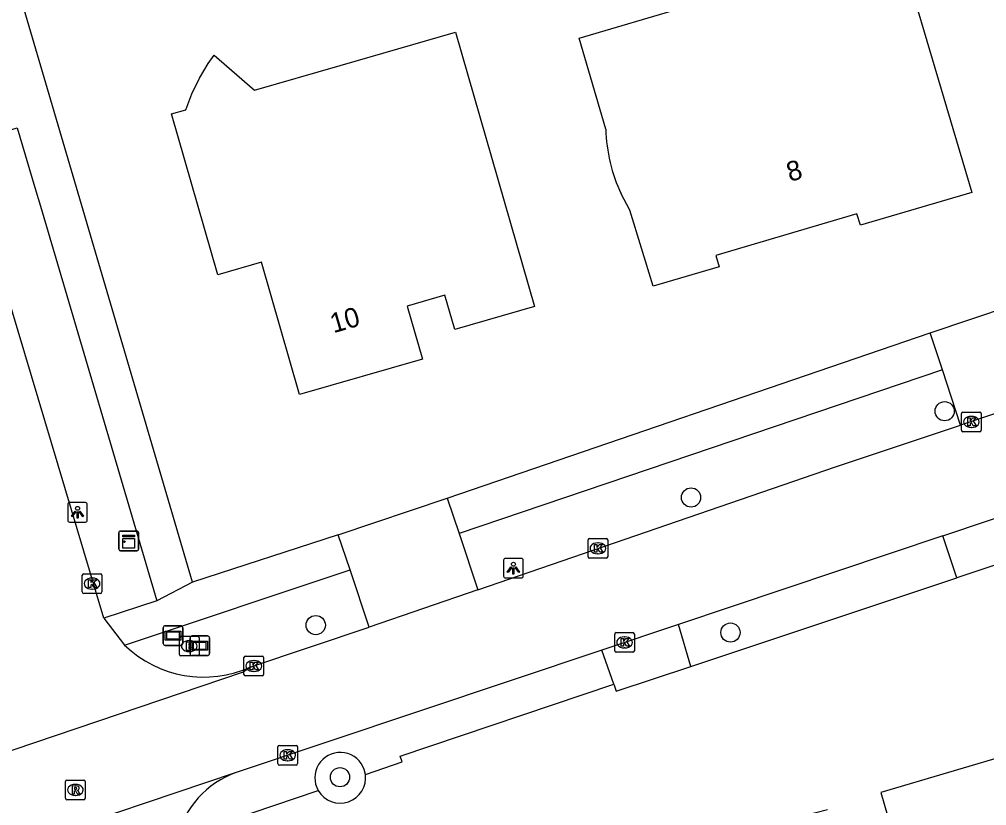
# Model space of a CAD drawing. Extents: x 162417 to 163721, y 384268 to 385416.
# Drawn here: x 163324.7 to 163373.92, y 384590.69 to 384630.72 of the extents above; entities that cross this region are included whole.
import ezdxf

# ---------------------------------------------------------------- set-up
doc = ezdxf.new("R2010")
doc.units = 0
for name, color, linetype in [('IMGEO_Boom', 7, 'Continuous'), ('IMGEO_Brandkraan', 7, 'Continuous'), ('IMGEO_Fietspad_open', 7, 'Continuous'), ('IMGEO_Groenvoorziening', 7, 'Continuous'), ('IMGEO_Haag', 7, 'Continuous'), ('IMGEO_Kast', 7, 'Continuous'), ('IMGEO_Kolk', 7, 'Continuous'), ('IMGEO_Lichtpunt', 7, 'Continuous'), ('IMGEO_Pand', 7, 'Continuous'), ('IMGEO_Pand_nummerreeks', 7, 'Continuous'), ('IMGEO_Rijbaan_lokaal_open', 7, 'Continuous'), ('IMGEO_Rioolput', 7, 'Continuous'), ('IMGEO_Straatnaambord', 7, 'Continuous'), ('IMGEO_Verklikker', 7, 'Continuous'), ('IMGEO_Voetpad_open', 7, 'Continuous')]:
    doc.layers.add(name, color=color, linetype=linetype)

msp = doc.modelspace()

# ---------------------------------------------------------------- linework, layer by layer
at = {"layer": 'IMGEO_Boom'}
for centre in [(163371.785, 384610.77), (163358.881, 384606.376), (163339.782, 384599.881), (163360.886, 384599.501), (163341.015, 384592.136)]:
    msp.add_circle(centre, 0.489, dxfattribs=at)
at = {"layer": 'IMGEO_Brandkraan'}
for p, q in [((163332.921, 384599.311), (163333.773, 384599.311)), ((163332.846, 384598.385), (163332.846, 384599.237)), ((163333.334, 384599.091), (163333.359, 384599.091)), ((163333.847, 384599.237), (163333.847, 384598.385)), ((163333.357, 384598.531), (163333.332, 384598.531)), ((163333.773, 384598.311), (163332.921, 384598.311))]:
    msp.add_line(p, q, dxfattribs=at)
for points in [[(163332.921, 384599.311), (163333.773, 384599.311)], [(163332.846, 384598.385), (163332.846, 384599.237)], [(163333.194, 384599.011), (163333.194, 384598.611), (163333.407, 384598.611)], [(163333.425, 384599.011), (163333.194, 384599.011)], [(163333.373, 384598.93), (163333.319, 384598.93), (163333.319, 384598.854)], [(163333.319, 384598.854), (163333.372, 384598.854)], [(163333.847, 384599.237), (163333.847, 384598.385)], [(163333.381, 384598.778), (163333.319, 384598.778), (163333.319, 384598.697)], [(163333.319, 384598.697), (163333.381, 384598.697)], [(163333.773, 384598.311), (163332.921, 384598.311)]]:
    msp.add_lwpolyline(points, dxfattribs=at)
for centre, radius, start, end in [((163332.923, 384599.235), 0.0765, 91.552, 178.448), ((163332.923, 384599.235), 0.0765, 91.552, 178.448), ((163333.771, 384599.235), 0.0765, 1.552, 88.448), ((163333.771, 384599.235), 0.0765, 1.552, 88.448), ((163333.374, 384598.892), 0.0379, 267.8285, 90.9355), ((163333.429, 384598.866), 0.145, 59.4692, 91.5367), ((163333.454, 384598.913), 0.0922, 285.5137, 58.1501), ((163333.459, 384598.721), 0.105, 301.3115, 78.989), ((163332.923, 384598.387), 0.0765, 181.552, 268.448), ((163332.923, 384598.387), 0.0765, 181.552, 268.448), ((163333.382, 384598.737), 0.0404, 269.8759, 90.5077), ((163333.413, 384598.862), 0.251, 268.6676, 293.5347), ((163333.771, 384598.387), 0.0765, 271.552, 358.448), ((163333.771, 384598.387), 0.0765, 271.552, 358.448)]:
    msp.add_arc(centre, radius, start, end, dxfattribs=at)
for centre, major_axis, ratio, start_param, end_param in [((163333.333, 384598.811), (-0.387, 0.002), 0.722429, 4.712389, 7.853982), ((163333.358, 384598.811), (-0.39, 0.002), 0.717154, 1.570796, 4.712389)]:
    msp.add_ellipse(centre, major_axis=major_axis, ratio=ratio, start_param=start_param, end_param=end_param, dxfattribs=at)
at = {"layer": 'IMGEO_Fietspad_open'}
msp.add_arc((163337.375, 384587.861), 4.809, 109.946, 166.0249, dxfattribs=at)
at = {"layer": 'IMGEO_Groenvoorziening'}
msp.add_lwpolyline([(163358.873, 384597.777), (163372.405, 384602.287)], dxfattribs=at)
at = {"layer": 'IMGEO_Haag'}
msp.add_arc((163341.028, 384592.106), 1.291, 209.9973, 7.8166, dxfattribs=at)
at = {"layer": 'IMGEO_Kast'}
for p, q in [((163329.764, 384603.741), (163329.764, 384604.582)), ((163329.764, 384604.582), (163329.764, 384603.741)), ((163329.839, 384604.666), (163330.68, 384604.666)), ((163330.68, 384604.666), (163329.839, 384604.666)), ((163330.764, 384604.591), (163330.764, 384603.75)), ((163330.764, 384603.75), (163330.764, 384604.591)), ((163330.689, 384603.666), (163329.848, 384603.666)), ((163329.848, 384603.666), (163330.689, 384603.666))]:
    msp.add_line(p, q, dxfattribs=at)
for points in [[(163329.959, 384604.456), (163330.559, 384604.456), (163330.559, 384604.371), (163329.959, 384604.371), (163329.959, 384604.456)], [(163329.959, 384604.281), (163330.559, 384604.281), (163330.559, 384603.792), (163329.959, 384603.792), (163329.959, 384604.281)]]:
    msp.add_lwpolyline(points, dxfattribs=at)
msp.add_circle((163330.043, 384604.13), 0.0377, dxfattribs=at)
for centre, start, end in [((163329.842, 384604.588), 92.4484, 184.2845), ((163329.842, 384604.588), 92.4484, 184.2845), ((163330.686, 384604.588), 2.4484, 94.2845), ((163330.686, 384604.588), 2.4484, 94.2845), ((163329.842, 384603.744), 182.4484, 274.2845), ((163329.842, 384603.744), 182.4484, 274.2845), ((163330.686, 384603.744), 272.4484, 4.2845), ((163330.686, 384603.744), 272.4484, 4.2845)]:
    msp.add_arc(centre, 0.0779, start, end, dxfattribs=at)
at = {"layer": 'IMGEO_Kolk'}
for p, q in [((163372.644, 384609.799), (163372.644, 384610.651)), ((163372.719, 384610.725), (163373.571, 384610.725)), ((163373.645, 384610.651), (163373.645, 384609.799)), ((163373.132, 384610.505), (163373.157, 384610.505)), ((163373.571, 384609.725), (163372.719, 384609.725)), ((163373.155, 384609.945), (163373.13, 384609.945)), ((163353.716, 384604.288), (163354.568, 384604.288)), ((163353.641, 384603.362), (163353.641, 384604.214)), ((163354.129, 384604.068), (163354.154, 384604.068)), ((163354.642, 384604.214), (163354.642, 384603.362)), ((163354.568, 384603.288), (163353.716, 384603.288)), ((163354.152, 384603.508), (163354.127, 384603.508)), ((163327.902, 384601.566), (163327.902, 384602.418)), ((163327.977, 384602.492), (163328.829, 384602.492)), ((163328.39, 384602.272), (163328.415, 384602.272)), ((163328.903, 384602.418), (163328.903, 384601.566)), ((163328.829, 384601.492), (163327.977, 384601.492)), ((163328.413, 384601.712), (163328.388, 384601.712)), ((163354.996, 384598.574), (163354.996, 384599.426)), ((163355.071, 384599.5), (163355.923, 384599.5)), ((163355.997, 384599.426), (163355.997, 384598.574)), ((163355.484, 384599.28), (163355.509, 384599.28)), ((163355.923, 384598.5), (163355.071, 384598.5)), ((163355.507, 384598.72), (163355.482, 384598.72)), ((163336.131, 384597.372), (163336.131, 384598.224)), ((163336.206, 384598.298), (163337.058, 384598.298)), ((163336.619, 384598.078), (163336.644, 384598.078)), ((163337.132, 384598.224), (163337.132, 384597.372)), ((163336.642, 384597.518), (163336.617, 384597.518)), ((163337.058, 384597.298), (163336.206, 384597.298)), ((163337.855, 384592.827), (163337.855, 384593.679)), ((163337.93, 384593.753), (163338.782, 384593.753)), ((163338.343, 384593.533), (163338.368, 384593.533)), ((163338.856, 384593.679), (163338.856, 384592.827)), ((163338.366, 384592.973), (163338.341, 384592.973)), ((163338.782, 384592.753), (163337.93, 384592.753))]:
    msp.add_line(p, q, dxfattribs=at)
for points in [[(163372.644, 384609.799), (163372.644, 384610.651)], [(163372.719, 384610.725), (163373.571, 384610.725)], [(163373.645, 384610.651), (163373.645, 384609.799)], [(163372.965, 384610.425), (163373.088, 384610.425), (163373.088, 384610.274), (163373.218, 384610.425), (163373.382, 384610.425), (163373.236, 384610.274), (163373.389, 384610.025), (163373.237, 384610.025), (163373.152, 384610.189), (163373.088, 384610.122), (163373.088, 384610.025), (163372.965, 384610.025), (163372.965, 384610.425)], [(163373.571, 384609.725), (163372.719, 384609.725)], [(163353.716, 384604.288), (163354.568, 384604.288)], [(163353.641, 384603.362), (163353.641, 384604.214)], [(163353.962, 384603.988), (163354.085, 384603.988), (163354.085, 384603.837), (163354.215, 384603.988), (163354.379, 384603.988), (163354.233, 384603.837), (163354.386, 384603.588), (163354.234, 384603.588), (163354.149, 384603.752), (163354.085, 384603.685), (163354.085, 384603.588), (163353.962, 384603.588), (163353.962, 384603.988)], [(163354.642, 384604.214), (163354.642, 384603.362)], [(163354.568, 384603.288), (163353.716, 384603.288)], [(163327.902, 384601.566), (163327.902, 384602.418)], [(163327.977, 384602.492), (163328.829, 384602.492)], [(163328.903, 384602.418), (163328.903, 384601.566)], [(163328.223, 384602.192), (163328.346, 384602.192), (163328.346, 384602.041), (163328.476, 384602.192), (163328.64, 384602.192), (163328.494, 384602.041), (163328.647, 384601.792), (163328.495, 384601.792), (163328.41, 384601.956), (163328.346, 384601.889), (163328.346, 384601.792), (163328.223, 384601.792), (163328.223, 384602.192)], [(163328.829, 384601.492), (163327.977, 384601.492)], [(163354.996, 384598.574), (163354.996, 384599.426)], [(163355.071, 384599.5), (163355.923, 384599.5)], [(163355.997, 384599.426), (163355.997, 384598.574)], [(163355.317, 384599.2), (163355.44, 384599.2), (163355.44, 384599.049), (163355.57, 384599.2), (163355.734, 384599.2), (163355.588, 384599.049), (163355.741, 384598.8), (163355.589, 384598.8), (163355.504, 384598.964), (163355.44, 384598.897), (163355.44, 384598.8), (163355.317, 384598.8), (163355.317, 384599.2)], [(163355.923, 384598.5), (163355.071, 384598.5)], [(163336.131, 384597.372), (163336.131, 384598.224)], [(163336.206, 384598.298), (163337.058, 384598.298)], [(163336.452, 384597.998), (163336.575, 384597.998), (163336.575, 384597.847), (163336.705, 384597.998), (163336.869, 384597.998), (163336.723, 384597.847), (163336.876, 384597.598), (163336.724, 384597.598), (163336.639, 384597.762), (163336.575, 384597.695), (163336.575, 384597.598), (163336.452, 384597.598), (163336.452, 384597.998)], [(163337.132, 384598.224), (163337.132, 384597.372)], [(163337.058, 384597.298), (163336.206, 384597.298)], [(163337.855, 384592.827), (163337.855, 384593.679)], [(163337.93, 384593.753), (163338.782, 384593.753)], [(163338.176, 384593.453), (163338.299, 384593.453), (163338.299, 384593.302), (163338.429, 384593.453), (163338.593, 384593.453), (163338.447, 384593.302), (163338.6, 384593.053), (163338.448, 384593.053), (163338.363, 384593.217), (163338.299, 384593.15), (163338.299, 384593.053), (163338.176, 384593.053), (163338.176, 384593.453)], [(163338.856, 384593.679), (163338.856, 384592.827)], [(163338.782, 384592.753), (163337.93, 384592.753)]]:
    msp.add_lwpolyline(points, dxfattribs=at)
for centre, start, end in [((163372.721, 384610.649), 91.552, 178.448), ((163372.721, 384610.649), 91.552, 178.448), ((163373.569, 384610.649), 1.552, 88.448), ((163373.569, 384610.649), 1.552, 88.448), ((163372.721, 384609.801), 181.552, 268.448), ((163372.721, 384609.801), 181.552, 268.448), ((163373.569, 384609.801), 271.552, 358.448), ((163373.569, 384609.801), 271.552, 358.448), ((163353.718, 384604.212), 91.552, 178.448), ((163353.718, 384604.212), 91.552, 178.448), ((163354.566, 384604.212), 1.552, 88.448), ((163354.566, 384604.212), 1.552, 88.448), ((163353.718, 384603.364), 181.552, 268.448), ((163353.718, 384603.364), 181.552, 268.448), ((163354.566, 384603.364), 271.552, 358.448), ((163354.566, 384603.364), 271.552, 358.448), ((163327.979, 384602.416), 91.552, 178.448), ((163327.979, 384602.416), 91.552, 178.448), ((163328.827, 384602.416), 1.552, 88.448), ((163328.827, 384602.416), 1.552, 88.448), ((163327.979, 384601.568), 181.552, 268.448), ((163327.979, 384601.568), 181.552, 268.448), ((163328.827, 384601.568), 271.552, 358.448), ((163328.827, 384601.568), 271.552, 358.448), ((163355.073, 384599.424), 91.552, 178.448), ((163355.073, 384599.424), 91.552, 178.448), ((163355.921, 384599.424), 1.552, 88.448), ((163355.921, 384599.424), 1.552, 88.448), ((163355.073, 384598.576), 181.552, 268.448), ((163355.073, 384598.576), 181.552, 268.448), ((163355.921, 384598.576), 271.552, 358.448), ((163355.921, 384598.576), 271.552, 358.448), ((163336.208, 384598.222), 91.552, 178.448), ((163336.208, 384598.222), 91.552, 178.448), ((163337.056, 384598.222), 1.552, 88.448), ((163337.056, 384598.222), 1.552, 88.448), ((163336.208, 384597.374), 181.552, 268.448), ((163336.208, 384597.374), 181.552, 268.448), ((163337.056, 384597.374), 271.552, 358.448), ((163337.056, 384597.374), 271.552, 358.448), ((163337.932, 384593.677), 91.552, 178.448), ((163337.932, 384593.677), 91.552, 178.448), ((163338.78, 384593.677), 1.552, 88.448), ((163338.78, 384593.677), 1.552, 88.448), ((163337.932, 384592.829), 181.552, 268.448), ((163337.932, 384592.829), 181.552, 268.448), ((163338.78, 384592.829), 271.552, 358.448), ((163338.78, 384592.829), 271.552, 358.448)]:
    msp.add_arc(centre, 0.0765, start, end, dxfattribs=at)
for centre, major_axis, ratio, start_param, end_param in [((163373.131, 384610.225), (-0.387, 0.002), 0.722429, 4.712389, 7.853982), ((163373.156, 384610.225), (-0.39, 0.002), 0.717154, 1.570796, 4.712389), ((163354.128, 384603.788), (-0.387, 0.002), 0.722429, 4.712389, 7.853982), ((163354.153, 384603.788), (-0.39, 0.002), 0.717154, 1.570796, 4.712389), ((163328.389, 384601.992), (-0.387, 0.002), 0.722429, 4.712389, 7.853982), ((163328.414, 384601.992), (-0.39, 0.002), 0.717154, 1.570796, 4.712389), ((163355.483, 384599), (-0.387, 0.002), 0.722429, 4.712389, 7.853982), ((163355.508, 384599), (-0.39, 0.002), 0.717154, 1.570796, 4.712389), ((163336.618, 384597.798), (-0.387, 0.002), 0.722429, 4.712389, 7.853982), ((163336.643, 384597.798), (-0.39, 0.002), 0.717154, 1.570796, 4.712389), ((163338.342, 384593.253), (-0.387, 0.002), 0.722429, 4.712389, 7.853982), ((163338.367, 384593.253), (-0.39, 0.002), 0.717154, 1.570796, 4.712389)]:
    msp.add_ellipse(centre, major_axis=major_axis, ratio=ratio, start_param=start_param, end_param=end_param, dxfattribs=at)
at = {"layer": 'IMGEO_Lichtpunt'}
for p, q in [((163327.162, 384606.025), (163327.162, 384605.218)), ((163327.162, 384606.025), (163327.162, 384605.218)), ((163328.064, 384606.12), (163327.256, 384606.12)), ((163328.064, 384606.12), (163327.256, 384606.12)), ((163328.158, 384605.218), (163328.158, 384606.025)), ((163328.158, 384605.218), (163328.158, 384606.025)), ((163327.256, 384605.124), (163328.064, 384605.124)), ((163327.256, 384605.124), (163328.064, 384605.124)), ((163350.244, 384603.276), (163349.436, 384603.276)), ((163350.244, 384603.276), (163349.436, 384603.276)), ((163349.342, 384603.181), (163349.342, 384602.374)), ((163349.342, 384603.181), (163349.342, 384602.374)), ((163350.338, 384602.374), (163350.338, 384603.181)), ((163350.338, 384602.374), (163350.338, 384603.181)), ((163349.436, 384602.28), (163350.244, 384602.28)), ((163349.436, 384602.28), (163350.244, 384602.28))]:
    msp.add_line(p, q, dxfattribs=at)
for points in [[(163327.536, 384605.689), (163327.575, 384605.661), (163327.387, 384605.399), (163327.349, 384605.426), (163327.536, 384605.689)], [(163327.638, 384605.641), (163327.685, 384605.641), (163327.685, 384605.319), (163327.638, 384605.319), (163327.638, 384605.641)], [(163327.748, 384605.661), (163327.786, 384605.688), (163327.973, 384605.426), (163327.934, 384605.398), (163327.748, 384605.661)], [(163349.716, 384602.845), (163349.755, 384602.817), (163349.567, 384602.555), (163349.529, 384602.582), (163349.716, 384602.845)], [(163349.818, 384602.797), (163349.865, 384602.797), (163349.865, 384602.475), (163349.818, 384602.475), (163349.818, 384602.797)], [(163349.928, 384602.817), (163349.966, 384602.844), (163350.153, 384602.582), (163350.114, 384602.554), (163349.928, 384602.817)]]:
    msp.add_lwpolyline(points, dxfattribs=at)
for centre in [(163327.661, 384605.823), (163349.841, 384602.979)]:
    msp.add_circle(centre, 0.0994, dxfattribs=at)
for centre, start, end in [((163327.256, 384606.025), 90, 180), ((163327.256, 384606.025), 90, 180), ((163328.064, 384606.025), 0, 90), ((163328.064, 384606.025), 0, 90), ((163327.256, 384605.218), 180, 270), ((163327.256, 384605.218), 180, 270), ((163328.064, 384605.218), 270, 0), ((163328.064, 384605.218), 270, 360), ((163349.436, 384603.181), 90, 180), ((163349.436, 384603.181), 90, 180), ((163350.244, 384603.181), 0, 90), ((163350.244, 384603.181), 0, 90), ((163349.436, 384602.374), 180, 270), ((163349.436, 384602.374), 180, 270), ((163350.244, 384602.374), 270, 0), ((163350.244, 384602.374), 270, 360)]:
    msp.add_arc(centre, 0.0946, start, end, dxfattribs=at)
at = {"layer": 'IMGEO_Pand'}
for points in [[(163354.543, 384625.127), (163353.186, 384629.758), (163369.415, 384634.561), (163371.747, 384626.703)], [(163350.916, 384616.107), (163346.854, 384614.936), (163346.352, 384616.675), (163344.429, 384616.12), (163345.208, 384613.419), (163338.963, 384611.616), (163337.021, 384618.356), (163334.807, 384617.718), (163332.449, 384625.902), (163333.165, 384626.108), (163333.478, 384626.928), (163333.86, 384627.718), (163334.308, 384628.472), (163334.611, 384628.896), (163336.658, 384627.116), (163341.022, 384628.374), (163346.891, 384630.066), (163350.916, 384616.107)], [(163371.747, 384626.703), (163373.169, 384621.909), (163367.504, 384620.235), (163367.319, 384620.817), (163360.137, 384618.695), (163360.316, 384618.12), (163356.948, 384617.133), (163355.771, 384621.007), (163355.324, 384621.829)], [(163365.825, 384590.479), (163364.706, 384590.192), (163360.682, 384589.023), (163362.106, 384584.231), (163363.586, 384579.248), (163364.755, 384575.318), (163371.456, 384577.31), (163370.27, 384581.226), (163369.845, 384582.664), (163373.698, 384583.805), (163374.124, 384582.367), (163377.865, 384583.474), (163379.028, 384579.543), (163384.859, 384581.269), (163382.561, 384589.036), (163381.143, 384593.83), (163380.557, 384593.672), (163380.59, 384593.387), (163375.844, 384591.998), (163375.427, 384593.399), (163368.54, 384591.356), (163369.07, 384589.543), (163367.915, 384589.188), (163367.599, 384590.132)]]:
    msp.add_lwpolyline(points, dxfattribs=at)
msp.add_arc((163362.771, 384625.334), 8.231, 181.4417, 205.2039, dxfattribs=at)
at = {"layer": 'IMGEO_Rijbaan_lokaal_open'}
for points in [[(163329.005, 384600.235), (163322.986, 384620.355), (163322.7, 384621.313), (163321.795, 384624.338)], [(163376.658, 384611.416), (163372.594, 384610.058)], [(163348.039, 384601.682), (163366.232, 384607.936), (163372.594, 384610.058)], [(163371.696, 384604.423), (163376.389, 384605.995)], [(163371.696, 384604.423), (163358.243, 384599.918)], [(163348.039, 384601.682), (163342.508, 384599.781)], [(163329.005, 384600.235), (163330.054, 384598.864)], [(163358.243, 384599.918), (163354.346, 384598.613)], [(163336.48, 384597.749), (163342.508, 384599.781)], [(163354.346, 384598.613), (163335.735, 384592.381)], [(163318.779, 384591.691), (163319.165, 384591.77), (163336.053, 384597.486), (163336.48, 384597.749)], [(163335.735, 384592.381), (163325.068, 384588.78)]]:
    msp.add_lwpolyline(points, dxfattribs=at)
msp.add_arc((163334.088, 384603.04), 5.807, 225.9892, 294.3236, dxfattribs=at)
at = {"layer": 'IMGEO_Rioolput'}
for p, q in [((163327.125, 384591.99), (163327.977, 384591.99)), ((163327.05, 384591.064), (163327.05, 384591.916)), ((163327.538, 384591.77), (163327.563, 384591.77)), ((163328.051, 384591.916), (163328.051, 384591.064)), ((163327.977, 384590.99), (163327.125, 384590.99)), ((163327.561, 384591.21), (163327.536, 384591.21))]:
    msp.add_line(p, q, dxfattribs=at)
for points in [[(163327.125, 384591.99), (163327.977, 384591.99)], [(163327.05, 384591.064), (163327.05, 384591.916)], [(163327.639, 384591.688), (163327.387, 384591.69), (163327.387, 384591.29)], [(163327.387, 384591.29), (163327.511, 384591.29), (163327.511, 384591.452), (163327.522, 384591.452)], [(163327.565, 384591.609), (163327.511, 384591.609), (163327.511, 384591.528)], [(163327.511, 384591.528), (163327.563, 384591.528)], [(163328.051, 384591.916), (163328.051, 384591.064)], [(163327.977, 384590.99), (163327.125, 384590.99)], [(163327.569, 384591.423), (163327.64, 384591.29), (163327.78, 384591.29), (163327.715, 384591.416)]]:
    msp.add_lwpolyline(points, dxfattribs=at)
for centre, radius, start, end in [((163327.127, 384591.914), 0.0765, 91.552, 178.448), ((163327.127, 384591.914), 0.0765, 91.552, 178.448), ((163327.975, 384591.914), 0.0765, 1.552, 88.448), ((163327.975, 384591.914), 0.0765, 1.552, 88.448), ((163327.521, 384591.399), 0.0533, 26.0293, 88.6989), ((163327.547, 384591.717), 0.19, 274.7715, 282.9687), ((163327.571, 384591.513), 0.0964, 77.0061, 93.1865), ((163327.585, 384591.57), 0.0378, 276.6634, 79.6772), ((163327.638, 384591.578), 0.109, 350.3612, 89.416), ((163327.636, 384591.578), 0.112, 277.5842, 350.9817), ((163327.62, 384591.363), 0.108, 29.5134, 73.7905), ((163327.127, 384591.066), 0.0765, 181.552, 268.448), ((163327.127, 384591.066), 0.0765, 181.552, 268.448), ((163327.975, 384591.066), 0.0765, 271.552, 358.448), ((163327.975, 384591.066), 0.0765, 271.552, 358.448)]:
    msp.add_arc(centre, radius, start, end, dxfattribs=at)
for centre, major_axis, ratio, start_param, end_param in [((163327.537, 384591.49), (-0.387, 0.002), 0.722429, 4.712389, 7.853982), ((163327.562, 384591.49), (-0.39, 0.002), 0.717154, 1.570796, 4.712389)]:
    msp.add_ellipse(centre, major_axis=major_axis, ratio=ratio, start_param=start_param, end_param=end_param, dxfattribs=at)
at = {"layer": 'IMGEO_Straatnaambord'}
for p, q in [((163332.126, 384599.848), (163332.916, 384599.848)), ((163332.916, 384599.848), (163332.126, 384599.848)), ((163332.026, 384598.948), (163332.026, 384599.748)), ((163332.026, 384599.748), (163332.026, 384598.948)), ((163333.016, 384599.748), (163333.016, 384598.948)), ((163333.016, 384598.948), (163333.016, 384599.748)), ((163332.916, 384598.848), (163332.126, 384598.848)), ((163332.126, 384598.848), (163332.916, 384598.848))]:
    msp.add_line(p, q, dxfattribs=at)
for points in [[(163332.127, 384599.58), (163332.915, 384599.58), (163332.915, 384599.116), (163332.127, 384599.116), (163332.127, 384599.58)], [(163332.192, 384599.515), (163332.192, 384599.181), (163332.85, 384599.181), (163332.85, 384599.515), (163332.192, 384599.515)]]:
    msp.add_lwpolyline(points, dxfattribs=at)
for centre, start, end in [((163332.126, 384599.748), 90, 180), ((163332.126, 384599.748), 90, 180), ((163332.916, 384599.748), 0, 90), ((163332.916, 384599.748), 360, 90), ((163332.126, 384598.948), 180, 270), ((163332.126, 384598.948), 180, 270), ((163332.916, 384598.948), 270, 0), ((163332.916, 384598.948), 270, 0)]:
    msp.add_arc(centre, 0.1, start, end, dxfattribs=at)
at = {"layer": 'IMGEO_Verklikker'}
for p, q in [((163333.487, 384599.33), (163334.277, 384599.33)), ((163334.277, 384599.33), (163333.487, 384599.33)), ((163333.387, 384598.43), (163333.387, 384599.23)), ((163333.387, 384599.23), (163333.387, 384598.43)), ((163334.377, 384599.23), (163334.377, 384598.43)), ((163334.377, 384598.43), (163334.377, 384599.23)), ((163334.277, 384598.33), (163333.487, 384598.33)), ((163333.487, 384598.33), (163334.277, 384598.33))]:
    msp.add_line(p, q, dxfattribs=at)
for points in [[(163333.488, 384599.062), (163334.276, 384599.062), (163334.276, 384598.598), (163333.488, 384598.598), (163333.488, 384599.062)], [(163333.553, 384598.997), (163333.553, 384598.663), (163334.211, 384598.663), (163334.211, 384598.997), (163333.553, 384598.997)]]:
    msp.add_lwpolyline(points, dxfattribs=at)
for centre, start, end in [((163333.487, 384599.23), 90, 180), ((163333.487, 384599.23), 90, 180), ((163334.277, 384599.23), 0, 90), ((163334.277, 384599.23), 360, 90), ((163333.487, 384598.43), 180, 270), ((163333.487, 384598.43), 180, 270), ((163334.277, 384598.43), 270, 0), ((163334.277, 384598.43), 270, 0)]:
    msp.add_arc(centre, 0.1, start, end, dxfattribs=at)
at = {"layer": 'IMGEO_Voetpad_open'}
for points in [[(163333.508, 384602.071), (163310.09, 384681.76), (163309.903, 384682.414)], [(163321.795, 384624.338), (163324.587, 384625.199), (163325.485, 384622.16), (163325.769, 384621.2), (163331.704, 384601.119)], [(163371.048, 384614.758), (163375.186, 384616.159)], [(163346.471, 384606.34), (163371.048, 384614.758)], [(163371.669, 384612.881), (163371.048, 384614.758)], [(163371.669, 384612.881), (163347.078, 384604.539)], [(163372.594, 384610.058), (163371.669, 384612.881)], [(163340.928, 384604.472), (163346.471, 384606.34)], [(163346.471, 384606.34), (163347.078, 384604.539)], [(163340.928, 384604.472), (163333.508, 384602.071)], [(163341.529, 384602.689), (163340.928, 384604.472)], [(163347.078, 384604.539), (163348.039, 384601.682)], [(163372.405, 384602.287), (163371.696, 384604.423)], [(163377.103, 384603.845), (163372.405, 384602.287)], [(163330.054, 384598.864), (163341.529, 384602.689)], [(163342.508, 384599.781), (163341.529, 384602.689)], [(163333.508, 384602.071), (163331.704, 384601.119)], [(163331.704, 384601.119), (163329.005, 384600.235)], [(163358.873, 384597.777), (163358.243, 384599.918)], [(163354.943, 384596.875), (163354.346, 384598.613)], [(163354.943, 384596.875), (163355.069, 384596.509), (163358.873, 384597.777)], [(163342.307, 384592.282), (163344.183, 384592.925), (163344.075, 384593.215), (163354.943, 384596.875)], [(163342.307, 384592.282), (163342.249, 384592.525)], [(163333.246, 384589.206), (163339.91, 384591.461)], [(163339.833, 384591.62), (163339.91, 384591.461)]]:
    msp.add_lwpolyline(points, dxfattribs=at)
msp.add_arc((163341.028, 384592.108), 1.291, 18.8729, 202.1976, dxfattribs=at)

# ---------------------------------------------------------------- texts
at = {"layer": 'IMGEO_Pand_nummerreeks'}
for s, rotation, p in [('8', 16.4603, (163363.911, 384622.437)), ('10', 16.1058, (163340.682, 384614.735))]:
    msp.add_text(s, height=1, rotation=rotation, dxfattribs=at).set_placement(p)

doc.saveas('drawing.dxf')
